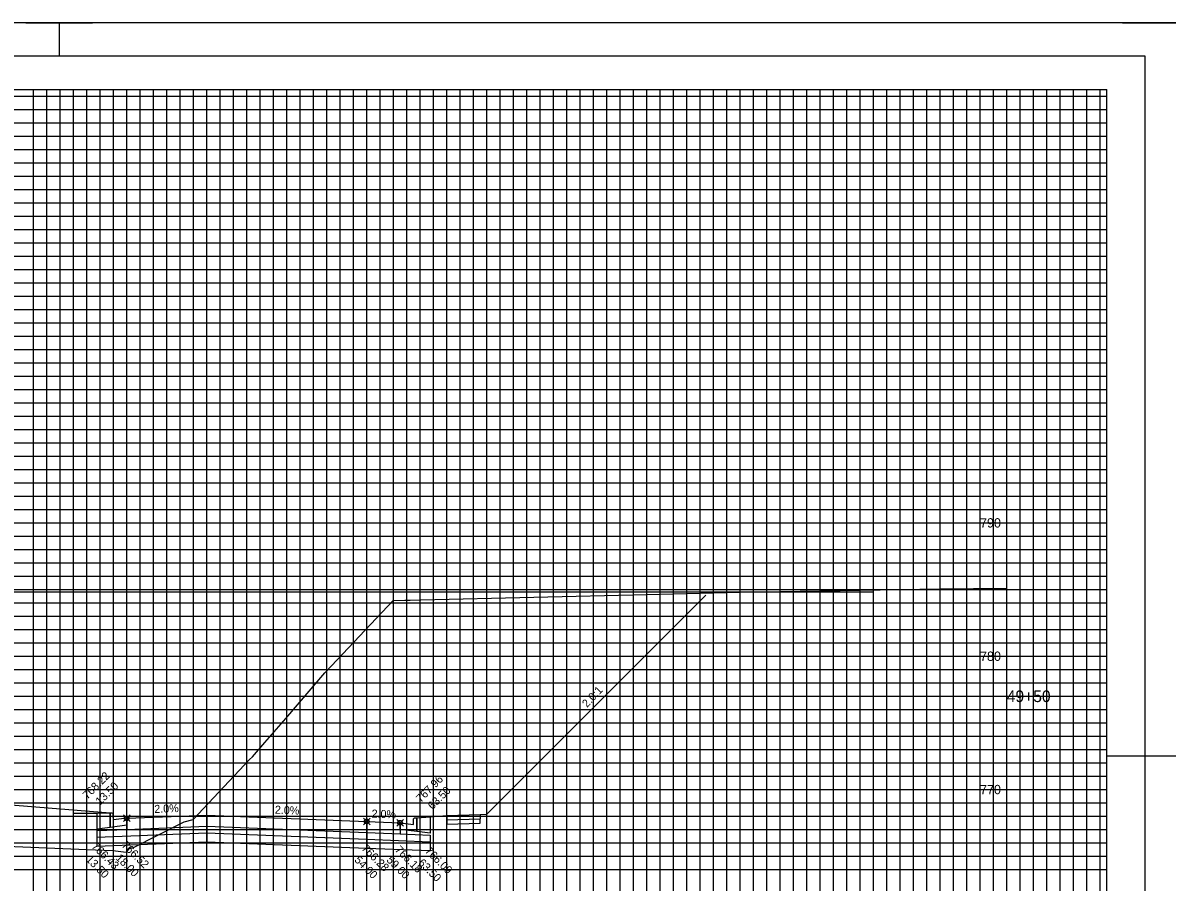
# Model space of a CAD drawing. Extents: x 578243 to 601557, y 174899 to 175559.
# Drawn here: x 600362.3 to 600533.9, y 174989.9 to 175118.8 of the extents above; entities that cross this region are included whole.
import ezdxf

# ---------------------------------------------------------------- set-up
doc = ezdxf.new("R2010")
doc.units = 0
for name, color, linetype in [('E_PROF_Grid', 7, 'Continuous'), ('E_PROF_GridMin', 7, 'Continuous'), ('P_CRDR_Label', 7, 'Continuous'), ('P_CRDR_Link', 7, 'Continuous'), ('P_E_XS_Ground', 7, 'Continuous'), ('P_RW_SlopeIntercepts', 7, 'Continuous'), ('P_XS_Text', 7, 'Continuous'), ('PLT_Sheet_Border', 7, 'Continuous'), ('PLT_Sheet_Info', 7, 'Continuous')]:
    doc.layers.add(name, color=color, linetype=linetype)

msp = doc.modelspace()

# ---------------------------------------------------------------- linework, layer by layer
at = {"layer": 'E_PROF_Grid'}
for p, q in [((600369.84, 174913.8), (600369.84, 175108.8)), ((600379.84, 174913.8), (600379.84, 175108.8)), ((600389.84, 174913.8), (600389.84, 175108.8)), ((600399.84, 174913.8), (600399.84, 175108.8)), ((600409.84, 174913.8), (600409.84, 175108.8)), ((600419.84, 174913.8), (600419.84, 175108.8)), ((600429.84, 174913.8), (600429.84, 175108.8)), ((600439.84, 174913.8), (600439.84, 175108.8)), ((600449.84, 174913.8), (600449.84, 175108.8)), ((600459.84, 174913.8), (600459.84, 175108.8)), ((600469.84, 174913.8), (600469.84, 175108.8)), ((600479.84, 174913.8), (600479.84, 175108.8)), ((600489.84, 174913.8), (600489.84, 175108.8)), ((600499.84, 174913.8), (600499.84, 175108.8)), ((600509.84, 174913.8), (600509.84, 175108.8)), ((600519.84, 174913.8), (600519.84, 175108.8)), ((600209.84, 175103.8), (600524.84, 175103.8)), ((600209.84, 175093.8), (600524.84, 175093.8)), ((600209.84, 175083.8), (600524.84, 175083.8)), ((600209.84, 175073.8), (600524.84, 175073.8)), ((600209.84, 175063.8), (600524.84, 175063.8)), ((600209.84, 175053.8), (600524.84, 175053.8)), ((600209.84, 175043.8), (600524.84, 175043.8)), ((600209.84, 175033.8), (600524.84, 175033.8)), ((600209.84, 175023.8), (600524.84, 175023.8)), ((600209.84, 175013.8), (600524.84, 175013.8)), ((600209.84, 175003.8), (600524.84, 175003.8)), ((600209.84, 174993.8), (600524.84, 174993.8))]:
    msp.add_line(p, q, dxfattribs=at)
at = {"layer": 'E_PROF_GridMin'}
for p, q in [((600363.84, 174913.8), (600363.84, 175108.8)), ((600365.84, 174913.8), (600365.84, 175108.8)), ((600367.84, 174913.8), (600367.84, 175108.8)), ((600371.84, 174913.8), (600371.84, 175108.8)), ((600373.84, 174913.8), (600373.84, 175108.8)), ((600375.84, 174913.8), (600375.84, 175108.8)), ((600377.84, 174913.8), (600377.84, 175108.8)), ((600381.84, 174913.8), (600381.84, 175108.8)), ((600383.84, 174913.8), (600383.84, 175108.8)), ((600385.84, 174913.8), (600385.84, 175108.8)), ((600387.84, 174913.8), (600387.84, 175108.8)), ((600391.84, 174913.8), (600391.84, 175108.8)), ((600393.84, 174913.8), (600393.84, 175108.8)), ((600395.84, 174913.8), (600395.84, 175108.8)), ((600397.84, 174913.8), (600397.84, 175108.8)), ((600401.84, 174913.8), (600401.84, 175108.8)), ((600403.84, 174913.8), (600403.84, 175108.8)), ((600405.84, 174913.8), (600405.84, 175108.8)), ((600407.84, 174913.8), (600407.84, 175108.8)), ((600411.84, 174913.8), (600411.84, 175108.8)), ((600413.84, 174913.8), (600413.84, 175108.8)), ((600415.84, 174913.8), (600415.84, 175108.8)), ((600417.84, 174913.8), (600417.84, 175108.8)), ((600421.84, 174913.8), (600421.84, 175108.8)), ((600423.84, 174913.8), (600423.84, 175108.8)), ((600425.84, 174913.8), (600425.84, 175108.8)), ((600427.84, 174913.8), (600427.84, 175108.8)), ((600431.84, 174913.8), (600431.84, 175108.8)), ((600433.84, 174913.8), (600433.84, 175108.8)), ((600435.84, 174913.8), (600435.84, 175108.8)), ((600437.84, 174913.8), (600437.84, 175108.8)), ((600441.84, 174913.8), (600441.84, 175108.8)), ((600443.84, 174913.8), (600443.84, 175108.8)), ((600445.84, 174913.8), (600445.84, 175108.8)), ((600447.84, 174913.8), (600447.84, 175108.8)), ((600451.84, 174913.8), (600451.84, 175108.8)), ((600453.84, 174913.8), (600453.84, 175108.8)), ((600455.84, 174913.8), (600455.84, 175108.8)), ((600457.84, 174913.8), (600457.84, 175108.8)), ((600461.84, 174913.8), (600461.84, 175108.8)), ((600463.84, 174913.8), (600463.84, 175108.8)), ((600465.84, 174913.8), (600465.84, 175108.8)), ((600467.84, 174913.8), (600467.84, 175108.8)), ((600471.84, 174913.8), (600471.84, 175108.8)), ((600473.84, 174913.8), (600473.84, 175108.8)), ((600475.84, 174913.8), (600475.84, 175108.8)), ((600477.84, 174913.8), (600477.84, 175108.8)), ((600481.84, 174913.8), (600481.84, 175108.8)), ((600483.84, 174913.8), (600483.84, 175108.8)), ((600485.84, 174913.8), (600485.84, 175108.8)), ((600487.84, 174913.8), (600487.84, 175108.8)), ((600491.84, 174913.8), (600491.84, 175108.8)), ((600493.84, 174913.8), (600493.84, 175108.8)), ((600495.84, 174913.8), (600495.84, 175108.8)), ((600497.84, 174913.8), (600497.84, 175108.8)), ((600501.84, 174913.8), (600501.84, 175108.8)), ((600503.84, 174913.8), (600503.84, 175108.8)), ((600505.84, 174913.8), (600505.84, 175108.8)), ((600507.84, 174913.8), (600507.84, 175108.8)), ((600511.84, 174913.8), (600511.84, 175108.8)), ((600513.84, 174913.8), (600513.84, 175108.8)), ((600515.84, 174913.8), (600515.84, 175108.8)), ((600517.84, 174913.8), (600517.84, 175108.8)), ((600521.84, 174913.8), (600521.84, 175108.8)), ((600523.84, 174913.8), (600523.84, 175108.8)), ((600209.84, 175107.8), (600524.84, 175107.8)), ((600209.84, 175105.8), (600524.84, 175105.8)), ((600209.84, 175101.8), (600524.84, 175101.8)), ((600209.84, 175099.8), (600524.84, 175099.8)), ((600209.84, 175097.8), (600524.84, 175097.8)), ((600209.84, 175095.8), (600524.84, 175095.8)), ((600209.84, 175091.8), (600524.84, 175091.8)), ((600209.84, 175089.8), (600524.84, 175089.8)), ((600209.84, 175087.8), (600524.84, 175087.8)), ((600209.84, 175085.8), (600524.84, 175085.8)), ((600209.84, 175081.8), (600524.84, 175081.8)), ((600209.84, 175079.8), (600524.84, 175079.8)), ((600209.84, 175077.8), (600524.84, 175077.8)), ((600209.84, 175075.8), (600524.84, 175075.8)), ((600209.84, 175071.8), (600524.84, 175071.8)), ((600209.84, 175069.8), (600524.84, 175069.8)), ((600209.84, 175067.8), (600524.84, 175067.8)), ((600209.84, 175065.8), (600524.84, 175065.8)), ((600209.84, 175061.8), (600524.84, 175061.8)), ((600209.84, 175059.8), (600524.84, 175059.8)), ((600209.84, 175057.8), (600524.84, 175057.8)), ((600209.84, 175055.8), (600524.84, 175055.8)), ((600209.84, 175051.8), (600524.84, 175051.8)), ((600209.84, 175049.8), (600524.84, 175049.8)), ((600209.84, 175047.8), (600524.84, 175047.8)), ((600209.84, 175045.8), (600524.84, 175045.8)), ((600209.84, 175041.8), (600524.84, 175041.8)), ((600209.84, 175039.8), (600524.84, 175039.8)), ((600209.84, 175037.8), (600524.84, 175037.8)), ((600209.84, 175035.8), (600524.84, 175035.8)), ((600209.84, 175031.8), (600524.84, 175031.8)), ((600209.84, 175029.8), (600524.84, 175029.8)), ((600209.84, 175027.8), (600524.84, 175027.8)), ((600209.84, 175025.8), (600524.84, 175025.8)), ((600209.84, 175021.8), (600524.84, 175021.8)), ((600209.84, 175019.8), (600524.84, 175019.8)), ((600209.84, 175017.8), (600524.84, 175017.8)), ((600209.84, 175015.8), (600524.84, 175015.8)), ((600209.84, 175011.8), (600524.84, 175011.8)), ((600209.84, 175009.8), (600524.84, 175009.8)), ((600209.84, 175007.8), (600524.84, 175007.8)), ((600209.84, 175005.8), (600524.84, 175005.8)), ((600209.84, 175001.8), (600524.84, 175001.8)), ((600209.84, 174999.8), (600524.84, 174999.8)), ((600209.84, 174997.8), (600524.84, 174997.8)), ((600209.84, 174995.8), (600524.84, 174995.8)), ((600209.84, 174991.8), (600524.84, 174991.8))]:
    msp.add_line(p, q, dxfattribs=at)
at = {"layer": 'P_CRDR_Label'}
for p, q in [((600377.35, 174999), (600378.34, 174999.99)), ((600377.35, 174999.99), (600378.34, 174999)), ((600413.35, 174998.52), (600414.34, 174999.51)), ((600413.35, 174999.51), (600414.34, 174998.52)), ((600418.35, 174998.32), (600419.34, 174999.31)), ((600418.35, 174999.31), (600419.34, 174998.32))]:
    msp.add_line(p, q, dxfattribs=at)
for centre in [(600377.84, 174999.5), (600413.84, 174999.02), (600418.84, 174998.82)]:
    msp.add_circle(centre, 0.35, dxfattribs=at)
at = {"layer": 'P_CRDR_Link'}
for p, q in [((600464.69, 175032.96), (600431.84, 175000.11)), ((600375.34, 175000.25), (600359.84, 175001.49)), ((600375.34, 175000.25), (600359.84, 175001.49)), ((600373.34, 175000.23), (600369.84, 175000.2)), ((600373.34, 175000.23), (600369.84, 175000.2)), ((600375.34, 175000.25), (600373.34, 175000.23)), ((600373.34, 175000.23), (600373.34, 174997.93)), ((600373.34, 175000.23), (600373.34, 174997.93)), ((600373.34, 175000.23), (600373.34, 174997.93)), ((600375.66, 175000.25), (600375.34, 175000.25)), ((600375.66, 175000.25), (600375.34, 175000.25)), ((600375.34, 175000.25), (600375.34, 174998.18)), ((600375.34, 174998.18), (600375.34, 175000.25)), ((600375.74, 175000.2), (600375.66, 175000.25)), ((600375.74, 175000.2), (600375.66, 175000.25)), ((600375.8, 175000.09), (600375.74, 175000.2)), ((600375.8, 175000.09), (600375.74, 175000.2)), ((600375.83, 174999.93), (600375.8, 175000.09)), ((600375.83, 174999.93), (600375.8, 175000.09)), ((600375.84, 174999.25), (600375.83, 174999.93)), ((600375.84, 174999.25), (600375.83, 174999.93)), ((600377.84, 174999.5), (600389.84, 174999.98)), ((600389.84, 174999.98), (600389.84, 174998.31)), ((600389.84, 174999.98), (600413.84, 174999.02)), ((600389.84, 174999.98), (600389.84, 174998.31)), ((600423.34, 174999.73), (600425.84, 174999.93)), ((600423.34, 174999.73), (600425.84, 174999.93)), ((600425.84, 174999.93), (600430.84, 175000.08)), ((600425.84, 174999.93), (600430.84, 175000.08)), ((600425.84, 174999.93), (600425.85, 174999.26)), ((600430.84, 175000.08), (600431.84, 175000.11)), ((600430.84, 175000.08), (600431.84, 175000.11)), ((600430.84, 175000.08), (600430.84, 174999.41)), ((600373.34, 174997.93), (600375.34, 174998.18)), ((600375.34, 174998.18), (600377.84, 174998.5)), ((600375.34, 174998.18), (600377.84, 174998.5)), ((600377.84, 174999.5), (600375.84, 174999.25)), ((600377.84, 174999.5), (600375.84, 174999.25)), ((600377.84, 174998.5), (600377.84, 174999.5)), ((600377.84, 174999.5), (600377.84, 174997.83)), ((600377.84, 174997.83), (600389.84, 174998.31)), ((600389.84, 174998.31), (600389.84, 174997.31)), ((600389.84, 174998.31), (600413.84, 174997.35)), ((600389.84, 174998.31), (600389.84, 174997.31)), ((600413.84, 174999.02), (600413.84, 174997.35)), ((600413.84, 174999.02), (600418.84, 174998.82)), ((600413.84, 174999.02), (600413.84, 174997.35)), ((600418.84, 174998.82), (600418.84, 174997.15)), ((600418.84, 174998.82), (600420.84, 174998.57)), ((600418.84, 174998.82), (600420.84, 174998.57)), ((600418.84, 174997.82), (600418.84, 174998.82)), ((600420.84, 174998.57), (600420.85, 174999.25)), ((600420.84, 174998.57), (600420.85, 174999.25)), ((600420.85, 174999.25), (600420.88, 174999.41)), ((600420.85, 174999.25), (600420.88, 174999.41)), ((600420.88, 174999.41), (600420.94, 174999.52)), ((600420.88, 174999.41), (600420.94, 174999.52)), ((600420.94, 174999.52), (600421.02, 174999.57)), ((600420.94, 174999.52), (600421.02, 174999.57)), ((600421.02, 174999.57), (600421.34, 174999.57)), ((600421.02, 174999.57), (600421.34, 174999.57)), ((600421.34, 174999.57), (600423.34, 174999.73)), ((600421.34, 174999.57), (600421.34, 174997.5)), ((600421.34, 174997.5), (600421.34, 174999.57)), ((600423.34, 174999.73), (600423.34, 174997.25)), ((600423.34, 174999.73), (600423.34, 174997.25)), ((600423.34, 174999.73), (600423.34, 174997.25)), ((600425.85, 174999.26), (600430.84, 174999.41)), ((600425.85, 174999.26), (600425.85, 174998.6)), ((600425.85, 174998.6), (600430.83, 174998.75)), ((600430.83, 174998.75), (600430.84, 174999.41)), ((600373.34, 174997.65), (600377.84, 174997.83)), ((600373.34, 174997.65), (600373.34, 174996.65)), ((600373.34, 174996.65), (600389.84, 174997.31)), ((600373.34, 174996.65), (600373.34, 174995.32)), ((600389.84, 174997.31), (600389.84, 174995.98)), ((600389.84, 174997.31), (600413.84, 174996.35)), ((600389.84, 174997.31), (600389.84, 174995.98)), ((600413.84, 174997.35), (600413.84, 174996.35)), ((600413.84, 174997.35), (600418.84, 174997.15)), ((600413.84, 174997.35), (600413.84, 174996.35)), ((600421.34, 174997.5), (600418.84, 174997.82)), ((600421.34, 174997.5), (600418.84, 174997.82)), ((600418.84, 174997.15), (600423.34, 174996.97)), ((600423.34, 174997.25), (600421.34, 174997.5)), ((600423.34, 174996.97), (600423.34, 174995.97)), ((600373.34, 174995.32), (600389.84, 174995.98)), ((600389.84, 174995.98), (600413.84, 174995.02)), ((600413.84, 174996.35), (600413.84, 174995.02)), ((600413.84, 174996.35), (600423.34, 174995.97)), ((600413.84, 174996.35), (600413.84, 174995.02)), ((600413.84, 174995.02), (600423.34, 174994.64)), ((600423.34, 174995.97), (600423.34, 174994.64))]:
    msp.add_line(p, q, dxfattribs=at)
at = {"layer": 'P_E_XS_Ground'}
msp.add_lwpolyline([(600359.84, 174995.3), (600371.84, 174994.82), (600375.78, 174994.66), (600377.78, 174994.41), (600378.36, 174995.08), (600378.78, 174995.08), (600378.78, 174995.08), (600386.44, 174998.94), (600387.8, 174999.31), (600387.82, 174999.32), (600387.82, 174999.32), (600396.25, 175008.33), (600396.71, 175008.72), (600396.71, 175008.72), (600398.55, 175010.87), (600401.69, 175014.48), (600401.7, 175014.48), (600407.56, 175021.31), (600407.7, 175021.46), (600417.83, 175032.15), (600417.83, 175032.15), (600419.55, 175032.2), (600420.35, 175032.21), (600421.95, 175032.26), (600455.83, 175033.08), (600469.92, 175033.43), (600499.8, 175033.9), (600509.84, 175034.03)], dxfattribs=at)
at = {"layer": 'P_RW_SlopeIntercepts'}
msp.add_line((600253.84, 175033.48), (600489.84, 175033.48), dxfattribs=at)
at = {"layer": 'PLT_Sheet_Border'}
for points in [[(600197.19, 174898.8), (600537.19, 174898.8), (600537.19, 175118.8), (600197.19, 175118.8)], [(600199.59, 174903.8), (600530.59, 174903.8), (600530.59, 175113.8), (600199.59, 175113.8)]]:
    msp.add_lwpolyline(points, close=True, dxfattribs=at)
at = {"layer": 'PLT_Sheet_Info'}
for p, q in [((600362.69, 175118.8), (600372.69, 175118.8)), ((600367.69, 175118.8), (600367.69, 175113.8)), ((600527.19, 175118.8), (600537.19, 175118.8)), ((600209.84, 175108.8), (600524.84, 175108.8)), ((600524.84, 174908.8), (600524.84, 175108.8)), ((600537.19, 175008.8), (600524.84, 175008.8))]:
    msp.add_line(p, q, dxfattribs=at)

# ---------------------------------------------------------------- texts
at = {"layer": 'P_CRDR_Label'}
for s, rotation, p in [('2.0:1', 46.711, (600446.88, 175016.02)), ('768.22', 45, (600371.93, 175002.27)), ('767.96', 45, (600421.93, 175001.77)), ('13.50', 45, (600373.87, 175001.39)), ('63.50', 45, (600423.7, 175000.71)), ('2.0%', 2.2906, (600382, 175000.28)), ('2.0%', 357.7094, (600400.05, 175000.19)), ('2.0%', 357.7094, (600414.55, 174999.61)), ('766.43', 315, (600372.49, 174995.17)), ('766.52', 315, (600376.99, 174995.35)), ('766.28', 315, (600412.99, 174994.87)), ('766.18', 315, (600417.99, 174994.67)), ('766.09', 315, (600422.49, 174994.49)), ('13.50', 315, (600371.61, 174993.23)), ('18.00', 315, (600376.08, 174993.44)), ('54.00', 315, (600411.9, 174993.14)), ('59.00', 315, (600416.72, 174993.12)), ('63.50', 315, (600421.46, 174992.7))]:
    msp.add_text(s, height=1.2, rotation=rotation, dxfattribs=at).set_placement(p)
at = {"layer": 'P_XS_Text'}
for s, height, p in [('790', 1.4, (600505.84, 175043.1)), ('780', 1.4, (600505.84, 175023.1)), ('49+50', 1.75, (600509.84, 175016.92)), ('770', 1.4, (600505.84, 175003.1))]:
    msp.add_text(s, height=height, rotation=360, dxfattribs=at).set_placement(p)

doc.saveas('drawing.dxf')
